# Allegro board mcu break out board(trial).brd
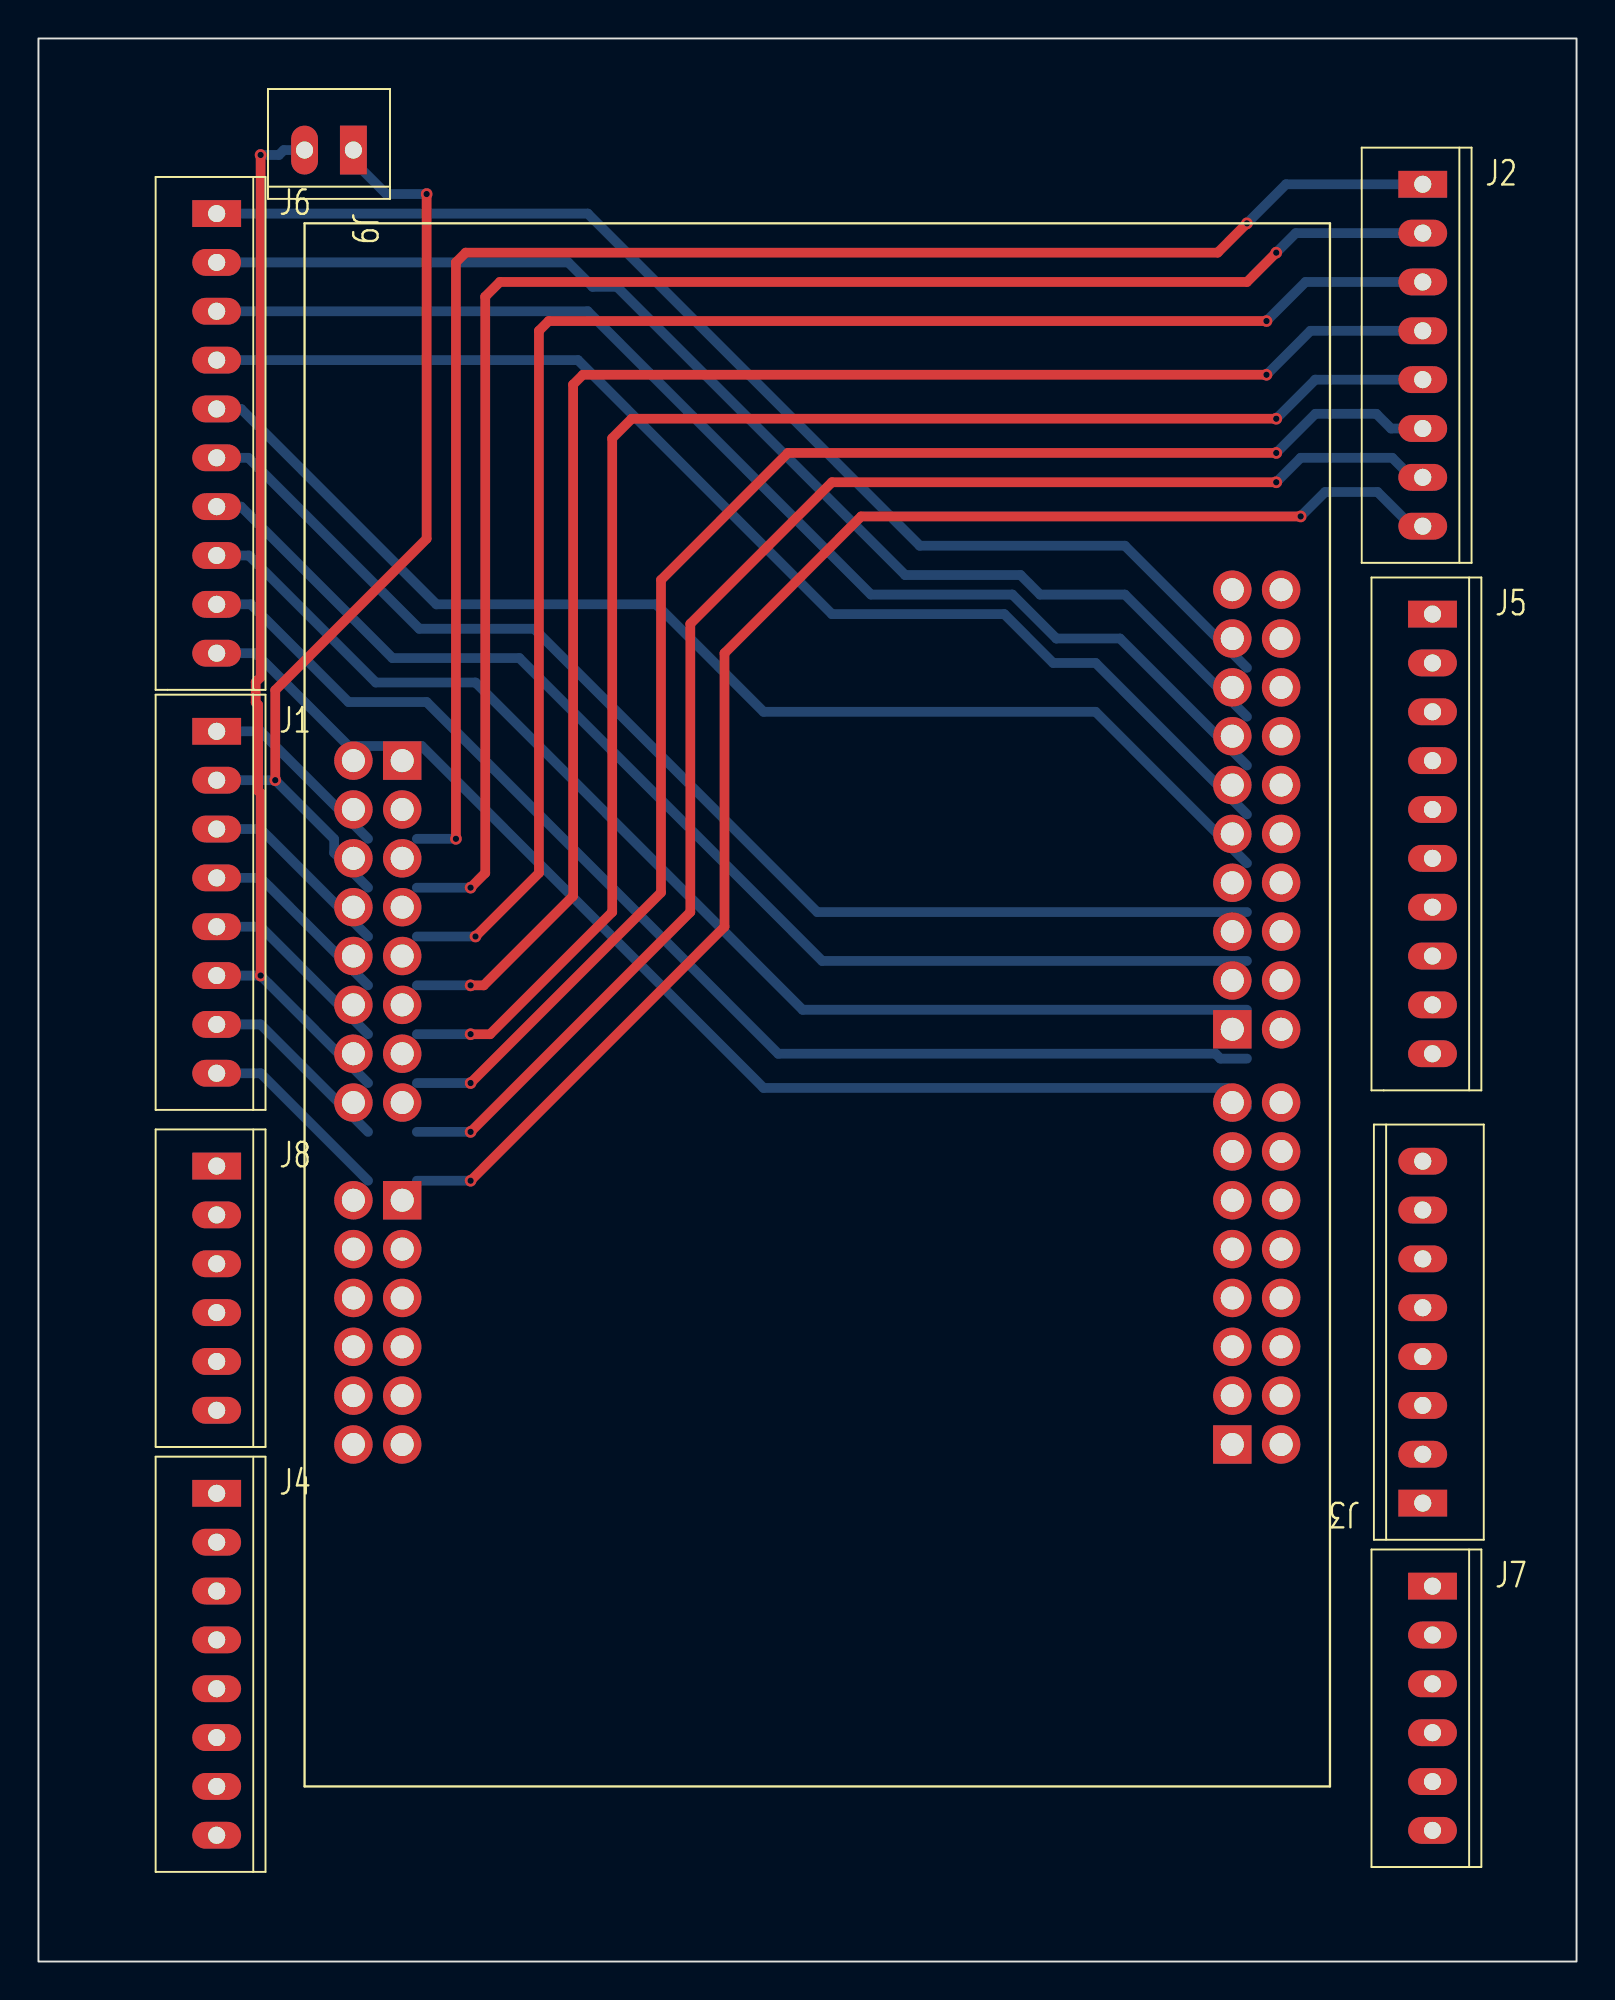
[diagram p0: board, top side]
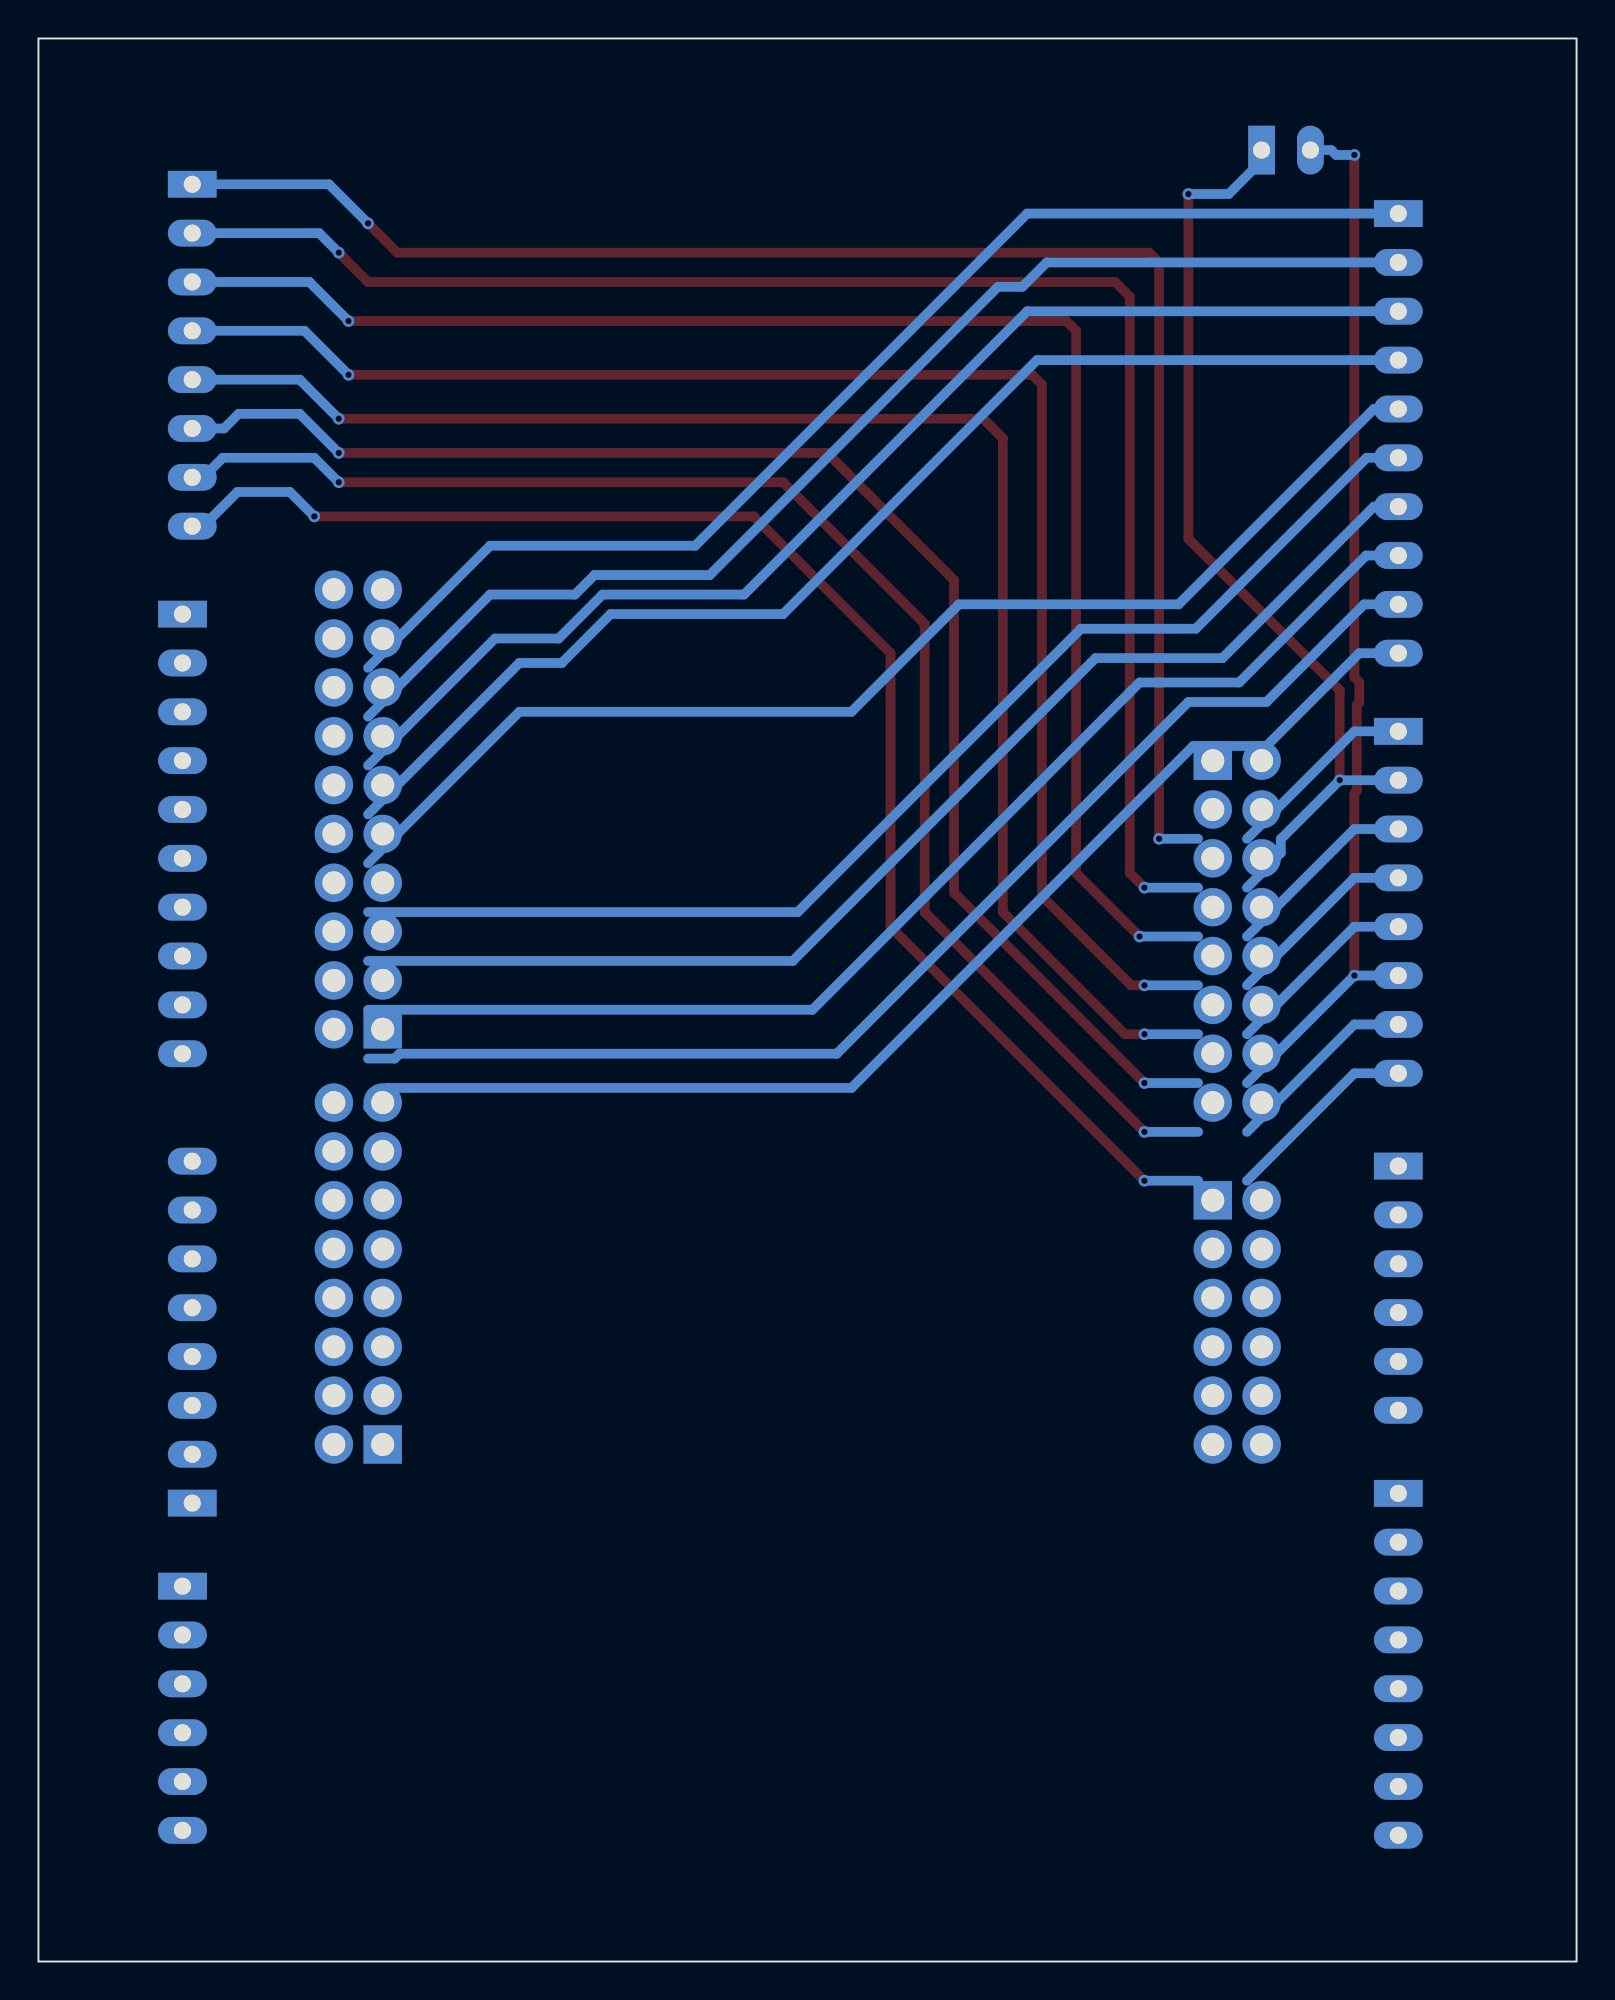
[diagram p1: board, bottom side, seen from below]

Outline 80.01 x 100 mm; copper layers: TOP, BOTTOM. Coordinates in mm from the lower left corner of the outline.
Outline path: rectangle 0,0 80.01,100

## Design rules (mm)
constraint set DEFAULT: min track width 0.508

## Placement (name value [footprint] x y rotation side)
J1  CON8  [GU-MOLEX8]  9.27 63.97 0 top
J2  CON8  [GU-MOLEX8]  72.01 92.42 0 top
J3  CON8  [GU-MOLEX8]  72.01 23.84 180 top
J4  CON8  [GU-MOLEX8]  9.27 24.35 0 top
J5  CON10  [GU-MOLEX10]  72.52 70.07 0 top
J6  CON10  [GU-MOLEX10]  9.27 90.89 0 top
J7  CON6  [GU-MOLEX6]  72.52 19.52 0 top
J8  CON6  [GU-MOLEX6]  9.27 41.36 0 top
J9  CON2  [GU-MOLEX2]  16.38 94.2 270 top
U2  FDRM-KL25Z DUAL  [GU-FRDM-KL25Z]  13.84 90.39 270 top

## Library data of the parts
J1-J4 = CON8
J5 J6 = CON10
J7 J8 = CON6
J9 = CON2
U2 = FDRM-KL25Z DUAL

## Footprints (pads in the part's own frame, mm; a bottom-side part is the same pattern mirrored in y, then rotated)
GU-FRDM-KL25Z
  rect 2x2 hole 1.2: J101(63.5,48.26) J201(41.91,48.26) J901(27.94,5.08) J1001(50.8,5.08)
  round 2 hole 1.2: J102(63.5,50.8) J103(60.96,48.26) J104(60.96,50.8) J105(58.42,48.26) J106(58.42,50.8) J107(55.88,48.26) J108(55.88,50.8) J109(53.34,48.26) J110(53.34,50.8) J111(50.8,48.26) J112(50.8,50.8) J113(48.26,48.26) J114(48.26,50.8) J115(45.72,48.26) J116(45.72,50.8) J202(41.91,50.8) J203(39.37,48.26) J204(39.37,50.8) J205(36.83,48.26) J206(36.83,50.8) J207(34.29,48.26) J208(34.29,50.8) J209(31.75,48.26) J210(31.75,50.8) J211(29.21,48.26) J212(29.21,50.8) J213(26.67,48.26) J214(26.67,50.8) J215(24.13,48.26) J216(24.13,50.8) J217(21.59,48.26) J218(21.59,50.8) J219(19.05,48.26) J220(19.05,50.8) J902(27.94,2.54) J903(30.48,5.08) J904(30.48,2.54) J905(33.02,5.08) J906(33.02,2.54) J907(35.56,5.08) J908(35.56,2.54) J909(38.1,5.08) J910(38.1,2.54) J911(40.64,5.08) J912(40.64,2.54) J913(43.18,5.08) J914(43.18,2.54) J915(45.72,5.08) J916(45.72,2.54) J1002(50.8,2.54) J1003(53.34,5.08) J1004(53.34,2.54) J1005(55.88,5.08) J1006(55.88,2.54) J1007(58.42,5.08) J1008(58.42,2.54) J1009(60.96,5.08) J1010(60.96,2.54) J1011(63.5,5.08) J1012(63.5,2.54)
GU-MOLEX2
  rect 2.54x1.397 hole 0.889: 1(0,0)
  oval 2.54x1.397 hole 0.889: 2(0,-2.54)
GU-MOLEX6
  rect 2.54x1.397 hole 0.889: 1(0,0)
  oval 2.54x1.397 hole 0.889: 2(0,-2.54) 3(0,-5.08) 4(0,-7.62) 5(0,-10.16) 6(0,-12.7)
GU-MOLEX8
  rect 2.54x1.397 hole 0.889: 1(0,0)
  oval 2.54x1.397 hole 0.889: 2(0,-2.54) 3(0,-5.08) 4(0,-7.62) 5(0,-10.16) 6(0,-12.7) 7(0,-15.24) 8(0,-17.78)
GU-MOLEX10
  rect 2.54x1.397 hole 0.889: 1(0,0)
  oval 2.54x1.397 hole 0.889: 2(0,-2.54) 3(0,-5.08) 4(0,-7.62) 5(0,-10.16) 6(0,-12.7) 7(0,-15.24) 8(0,-17.78) 9(0,-20.32) 10(0,-22.86)

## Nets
GND: J1.6 J1.7 J9.2 U2.J912 U2.J914
POWER: J1.2 J9.1 U2.J904
N00971: J1.1 U2.J902
N00975: J1.3 U2.J906
N00977: J1.4 U2.J908
N00979: J1.5 U2.J910
N00985: J1.8 U2.J916
N01053: J2.1 U2.J901
N01055: J2.2 U2.J903
N01057: J2.3 U2.J905
N01059: J2.4 U2.J907
N01061: J2.5 U2.J909
N01063: J2.6 U2.J911
N01065: J2.7 U2.J913
N01067: J2.8 U2.J915
N01138: J7.1 U2.J1001
N01140: J7.2 U2.J1003
N01142: J7.3 U2.J1005
N01144: J7.4 U2.J1007
N01146: J7.5 U2.J1009
N01148: J7.6 U2.J1011
N01262: J8.1 U2.J1002
N01268: J8.2 U2.J1004
N01274: J8.3 U2.J1006
N01280: J8.4 U2.J1008
N01286: J8.5 U2.J1010
N01292: J8.6 U2.J1012
N01663: J6.1 U2.J219
N01669: J6.2 U2.J217
N01675: J6.3 U2.J215
N01681: J6.4 U2.J213
N01687: J6.5 U2.J211
N01693: J6.6 U2.J209
N01699: J6.7 U2.J207
N01705: J6.8 U2.J205
N01711: J6.9 U2.J203
N01717: J6.10 U2.J201
N01937: J3.1 U2.J102
N01939: J3.2 U2.J104
N01941: J3.3 U2.J106
N01943: J3.4 U2.J108
N01945: J3.5 U2.J110
N01947: J3.6 U2.J112
N01949: J3.7 U2.J114
N01951: J3.8 U2.J116
N03369: J5.1 U2.J220
N03375: J5.2 U2.J218
N03381: J5.3 U2.J216(VREFH)
N03387: J5.4 U2.J214
N03393: J5.5 U2.J212
N03399: J5.6 U2.J210
N03405: J5.7 U2.J208
N03411: J5.8 U2.J206
N03417: J5.9 U2.J204
N03423: J5.10 U2.J202
N004490: J4.8 U2.J101
N004491: J4.7 U2.J103
N004492: J4.6 U2.J105
N004493: J4.5 U2.J107
N004494: J4.4 U2.J109
N004495: J4.3 U2.J111
N004496: J4.2 U2.J113
N004497: J4.1 U2.J115

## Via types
v1: diameter 0.61, hole 0.33, TOP to BOTTOM, 20 vias

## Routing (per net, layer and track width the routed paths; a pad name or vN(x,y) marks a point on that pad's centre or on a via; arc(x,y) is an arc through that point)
GND: length 65.7
  TOP w0.508: v1(11.56,51.27) 11.56,60.76 11.43,60.88 11.43,65.35 11.3,65.47 11.3,66.53 11.56,66.79 v1(11.56,93.94)
  BOTTOM w0.508: 17.15,45.68 v1(11.56,51.27) J1.6 ; J1.7 11.56,48.73 17.15,43.14 ; v1(11.56,93.94) 12.51,93.94 12.76,94.2 J9.2
POWER: length 49.5
  TOP w0.508: v1(20.19,91.91) 20.19,73.98 12.32,66.11 v1(12.32,61.43)
  BOTTOM w0.508: v1(20.19,91.91) 18.1,91.91 16.38,93.62 J9.1 ; J1.2 v1(12.32,61.43) 15.38,58.37 15.38,57.65 16.17,56.87 16.17,56.82 17.15,55.84
N00971: length 10.2
  BOTTOM w0.508: 17.15,58.38 11.56,63.97 J1.1
N00975: length 10.2
  BOTTOM w0.508: 17.15,53.3 11.56,58.89 J1.3
N00977: length 10.2
  BOTTOM w0.508: J1.4 11.56,56.35 17.15,50.76
N00979: length 10.2
  BOTTOM w0.508: 17.15,48.22 11.56,53.81 J1.5
N00985: length 10.2
  BOTTOM w0.508: J1.8 11.56,46.19 17.15,40.6
N01053: length 84
  TOP w0.508: v1(21.72,58.38) 21.72,88.35 22.23,88.86 61.34,88.86 v1(62.87,90.39)
  BOTTOM w0.508: 19.69,58.38 v1(21.72,58.38) ; J2.1 64.9,92.42 v1(62.87,90.39)
N01055: length 84
  TOP w0.508: v1(64.39,88.86) 62.87,87.34 24,87.34 23.24,86.58 23.24,56.6 v1(22.48,55.84)
  BOTTOM w0.508: v1(64.39,88.86) 65.41,89.88 J2.2 ; 19.69,55.84 v1(22.48,55.84)
N01057: length 82.9
  TOP w0.508: v1(22.73,53.3) 26.04,56.6 26.04,84.8 26.54,85.31 v1(63.88,85.31)
  BOTTOM w0.508: v1(63.88,85.31) 65.91,87.34 J2.3 ; 19.69,53.3 v1(22.73,53.3)
N01059: length 82
  TOP w0.508: v1(22.48,50.76) 23.16,50.76 27.81,55.41 27.81,82 28.32,82.51 v1(63.88,82.51)
  BOTTOM w0.508: v1(22.48,50.76) 19.69,50.76 ; J2.4 66.17,84.8 v1(63.88,82.51)
N01061: length 80.9
  TOP w0.508: v1(22.48,48.22) 23.5,48.22 29.85,54.57 29.85,79.21 30.86,80.23 v1(64.39,80.23)
  BOTTOM w0.508: v1(64.39,80.23) 66.42,82.26 J2.5 ; v1(22.48,48.22) 19.69,48.22
N01063: length 76.6
  TOP w0.508: v1(22.48,45.68) 32.39,55.59 32.39,71.84 38.99,78.45 v1(64.39,78.45)
  BOTTOM w0.508: 19.69,45.68 v1(22.48,45.68) ; J2.6 70.36,79.72 69.6,80.48 66.42,80.48 v1(64.39,78.45)
N01065: length 76
  TOP w0.508: v1(64.39,76.92) 41.28,76.92 33.91,69.56 33.91,54.57 v1(22.48,43.14)
  BOTTOM w0.508: J2.7 71.44,77.18 70.42,78.19 65.66,78.19 v1(64.39,76.92) ; 19.69,43.14 v1(22.48,43.14)
N01067: length 76.2
  TOP w0.508: v1(22.48,40.6) 35.69,53.81 35.69,68.03 42.8,75.15 v1(65.66,75.15)
  BOTTOM w0.508: J2.8 71.44,74.64 69.66,76.42 66.93,76.42 v1(65.66,75.15) ; 19.69,40.6 v1(22.48,40.6)
N01663: length 63.4
  BOTTOM w0.508: J6.1 28.58,90.89 45.85,73.62 56.52,73.62 62.87,67.27
N01669: length 63.4
  BOTTOM w0.508: J6.2 27.56,88.35 28.83,87.08 30.1,87.08 45.09,72.1 51.09,72.1 52.1,71.08 56.52,71.08 62.87,64.73
N01675: length 63.4
  BOTTOM w0.508: J6.3 28.58,85.81 43.31,71.08 50.67,71.08 52.95,68.8 56.26,68.8 62.87,62.19
N01681: length 63.4
  BOTTOM w0.508: J6.4 28.07,83.27 41.28,70.07 50.24,70.07 52.78,67.53 54.99,67.53 62.87,59.65
N01687: length 63.4
  BOTTOM w0.508: J6.5 10.54,80.73 20.7,70.57 32.13,70.57 37.72,64.99 54.99,64.99 62.87,57.11
N01693: length 63.4
  BOTTOM w0.508: J6.6 10.92,78.19 19.81,69.3 25.78,69.3 40.51,54.57 62.87,54.57
N01699: length 63.4
  BOTTOM w0.508: 62.87,52.03 40.77,52.03 25.02,67.78 18.42,67.78 10.54,75.65 J6.7
N01705: length 63.4
  BOTTOM w0.508: 62.87,49.49 39.75,49.49 22.73,66.51 17.55,66.51 10.95,73.11 J6.8
N01711: length 63.4
  BOTTOM w0.508: J6.9 11.05,70.57 16.13,65.49 20.19,65.49 38.48,47.21 61.23,47.21 61.48,46.95 62.87,46.95
N01717: length 63.4
  BOTTOM w0.508: J6.10 11.3,68.03 16.13,63.21 19.94,63.21 37.72,45.43 61.85,45.43 62.87,44.41
